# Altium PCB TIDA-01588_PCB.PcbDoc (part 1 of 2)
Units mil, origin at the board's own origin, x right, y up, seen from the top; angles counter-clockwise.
Board outline 787.4 x 472.44 mil, 2 copper layers (Top Layer, Bottom Layer), stack 62 mil thick; 49 components, 26 nets, 145 pads, 54 vias.
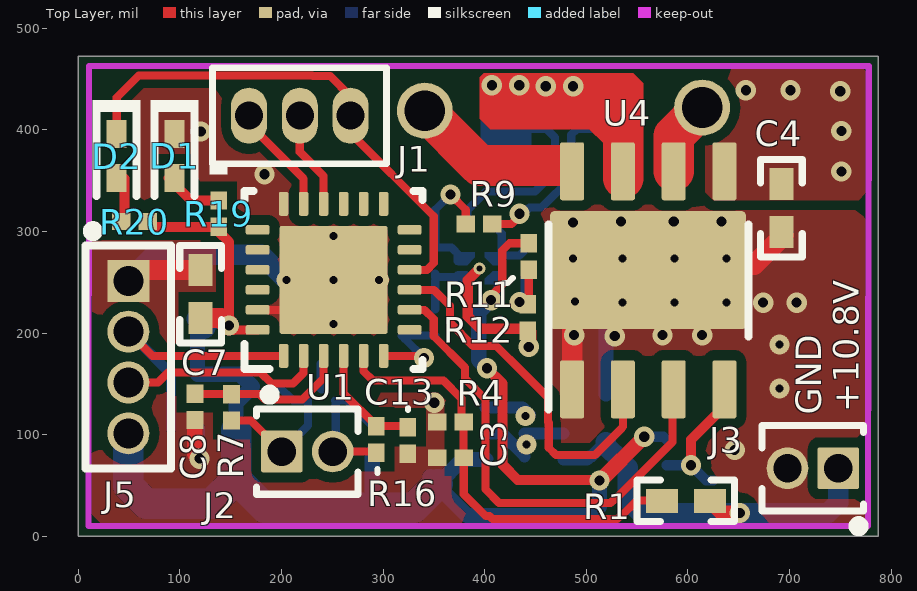
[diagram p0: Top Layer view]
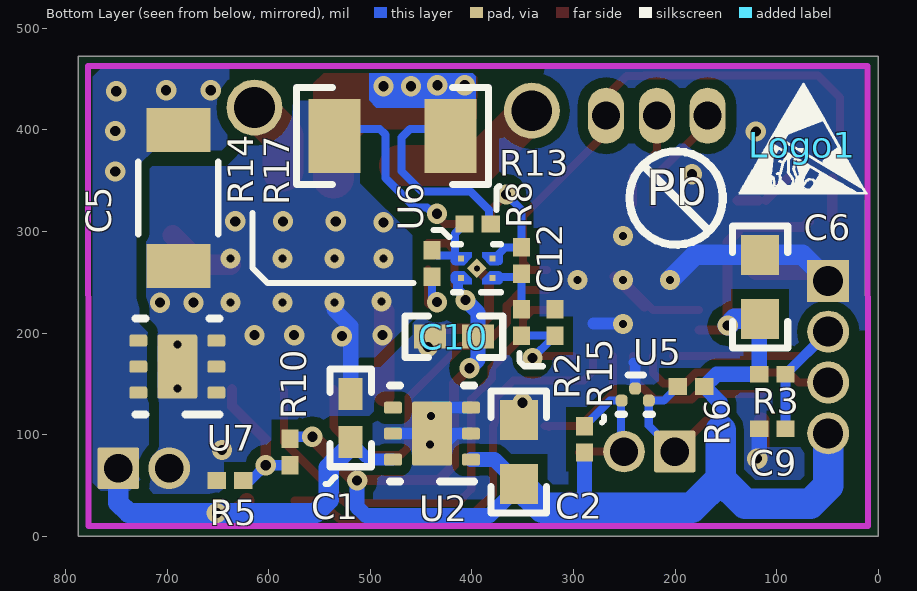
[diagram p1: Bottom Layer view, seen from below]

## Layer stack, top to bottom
Top Solder: solder mask 0.4, Solder Resist, Dk 3.5
Top Layer: signal copper 1.4
Dielectric1: core 59.2, FR-4 High Tg, Dk 4.8
Bottom Layer: signal copper 1.4
Bottom Solder: solder mask 0.4, Solder Resist, Dk 3.5

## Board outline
0,0 0,472.44 787.4,472.44 787.4,0

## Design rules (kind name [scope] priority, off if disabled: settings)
AcuteAngle [All] p1: minimum=4.50000000000000E+0001 checktracksonly=FALSE
AssemblyTestPointUsage [All] p1: valid=2
BoardOutlineClearance BoardOutlineClearance_MountingHoles [OnCopper and InComponentClass('Mounting Holes')] p1: gap=40 ignorepadtopadclearanceinfootprint=FALSE
BoardOutlineClearance BoardOutlineClearance_Poly [OnCopper and IsPoly] p2: gap=10 ignorepadtopadclearanceinfootprint=FALSE
BoardOutlineClearance [OnCopper and Not InComponentClass('Logo') and not InComponentClass('FiducialMark') and not InRegion(1000,500,4000,800) and not InPoly] p3: gap=8 ignorepadtopadclearanceinfootprint=FALSE
Clearance Clearance_1 [IsKeepOut] p1: gap=0 ignorepadtopadclearanceinfootprint=FALSE
Clearance Clearance_Keepouts [((IsTrack Or IsArc) And Not InPoly) And IsFree and IsKeepOut vs ((IsTrack Or IsArc) And Not InPoly) And IsFree and IsKeepOut] p2: gap=0 ignorepadtopadclearanceinfootprint=FALSE
Clearance Clearance_Poly [InPolygon] p3: gap=10 ignorepadtopadclearanceinfootprint=FALSE except(0: Arc-Hole Track-Hole SMDPad-Hole THPad-Hole Via-Hole Fill-Hole Poly-Hole Region-Hole Text-Hole; 8: Track-Poly; 15: Fill-Text Poly-Text Region-Text)
Clearance Clearance_FiducialMark [IsKeepOut and InComponentClass('FiducialMark') vs IsPad and InComponentClass('FiducialMark')] p4: gap=0 ignorepadtopadclearanceinfootprint=FALSE
Clearance [All] p5: gap=7.87 ignorepadtopadclearanceinfootprint=FALSE except(0: Arc-Hole Track-Hole SMDPad-Hole THPad-Hole Via-Hole Fill-Hole Poly-Hole Region-Hole Text-Hole)
ComponentClearance ComponentClearance_MountingHoles_FiducialMarks [InComponentClass('Mounting Holes') vs InComponentClass('FiducialMark')] p1: gap=50 collisioncheckmode=3 verticalgap=10 showdistances=FALSE
ComponentClearance ComponentClearance_Shunt [InComponentClass('Header') vs InComponentClass('Shunt')] p2: gap=0 collisioncheckmode=3 verticalgap=0 showdistances=FALSE
ComponentClearance ComponentClearance_Logo [InComponentClass('Logo')] p3: gap=50 collisioncheckmode=3 verticalgap=10 showdistances=FALSE
ComponentClearance ComponentClearance_ScrewToNut [(HasFootprint('NY PMS 440 0025 PH')) vs (HasFootprint('Keystone_1902C'))] p4: gap=5 collisioncheckmode=3 verticalgap=10 showdistances=FALSE
ComponentClearance ComponentClearance_MountingHoles [InComponentClass('Mounting Holes')] p5: gap=250 collisioncheckmode=3 verticalgap=100000 showdistances=FALSE
ComponentClearance ComponentClearance_SmallPassives [HasFootprint('0201*') or HasFootprint('0402*') or HasFootprint('0508') or HasFootprint('0603*') or HasFootprint('0612') or HasFootprint('0805*') or HasFootprint('0815*') or HasFootprint('0830*') or HasFootprint('1206*') or HasFootprint('1210*') or HasFootprint('1808*') or HasFootprint('1812*') or HasFootprint('1825*') or HasFootprint('2010*') or HasFootprint('2220*') or HasFootprint('2225*') or HasFootprint('2512*') or HasFootprint('2728*') or HasFootprint('3518*') vs HasFootprint('0201*') or HasFootprint('0402*') or HasFootprint('0508') or HasFootprint('0603*') or HasFootprint('0612') or HasFootprint('0805*') or HasFootprint('0815*') or HasFootprint('0830*') or HasFootprint('1206*') or HasFootprint('1210*') or HasFootprint('1808*') or HasFootprint('1812*') or HasFootprint('1825*') or HasFootprint('2010*') or HasFootprint('2220*') or HasFootprint('2225*') or HasFootprint('2512*') or HasFootprint('2728*') or HasFootprint('3518*')] p6: gap=14.96 collisioncheckmode=3 verticalgap=10 showdistances=FALSE
ComponentClearance ComponentClearance_THtoSMT [IsThruComponent vs IsSMTComponent] p7: gap=10 collisioncheckmode=3 verticalgap=10 showdistances=FALSE
ComponentClearance ComponentClearance_THtoTH [IsThruComponent vs IsThruComponent] p8: gap=8 collisioncheckmode=3 verticalgap=8 showdistances=FALSE
ComponentClearance [All] p9: gap=10 collisioncheckmode=3 verticalgap=10 showdistances=FALSE
DiffPairsRouting [All] p1: maxlimit=100 minlimit=10 mostfreqgap=10 toplayer_minwidth=15 toplayer_maxwidth=15 toplayer_prefwidth=15 bottomlayer_minwidth=15 bottomlayer_maxwidth=15 bottomlayer_prefwidth=15 maxuncoupledlength=1000
FabricationTestPointUsage TestPointUsage [All] p1: valid=2 allowmultiple=FALSE
FabricationTestpoint Testpoint [All] p1: side=3 testpointundercomponent=TRUE minsize=40 maxsize=100 preferedsize=60 minholesize=0 maxholesize=40 preferedholesize=32 testpointgrid=1 allowsidetop=TRUE allowsidebottom=TRUE usegrid=TRUE gridtolerance=0.01
FanoutControl Fanout_LCC [IsLCC] p1: bgadir=Out bgaviamode=Centered fanoutstyle=Auto fanoutdirection=Alternating viagrid=1 // Fanout_LCC (Default Rule)
FanoutControl Fanout_BGA [IsBGA] p2: bgadir=Out bgaviamode=Centered fanoutstyle=Auto fanoutdirection=Alternating viagrid=1 // Fanout_BGA (Default Rule)
FanoutControl Fanout_Default [All] p4: bgadir=Out bgaviamode=Centered fanoutstyle=Auto fanoutdirection=Alternating viagrid=1 // Fanout_Default (Default Rule)
FanoutControl Fanout_Small [(CompPinCount < 5)] p5: bgadir=Out bgaviamode=Centered fanoutstyle=Auto fanoutdirection=OutThenIn viagrid=1 // Fanout_Small (Default Rule)
HoleSize [All] p1: absolutevalues=TRUE maxlimit=251 minlimit=7.87 maxpercent=80.000 minpercent=20.000
MinimumAnnularRing MinimumAnnularRing_ThermalPadVias [IsVia and InAnyComponent] p1: minimumring=5.91
MinimumAnnularRing [All] p2: minimumring=8
MinimumSolderMaskSliver MinimumSolderMaskSliver_Logo [InComponentClass('Logo') vs InComponentClass('Logo')] p1: minsoldermaskwidth=0.7
MinimumSolderMaskSliver [All] p2: minsoldermaskwidth=3.94
PlaneConnect [All] p1: planeconnectstyle=Direct reliefexpansion=10 reliefentries=4 reliefconductorwidth=10 reliefairgap=10
PolygonConnect [All] p1: connectstyle=Direct reliefconductorwidth=10 reliefentries=4 polygonreliefangle="90 Angle" airgapwidth=10
RoutingVias ThermalPadVias [IsVia and InAnyComponent] p1: holewidth=7.87 width=19.68 viastyle="Through Hole" minholewidth=7.87 minwidth=19.68 maxholewidth=12.99 maxwidth=23.62
RoutingVias [All] p2: holewidth=10 width=20 viastyle="Through Hole" minholewidth=8 minwidth=18 maxholewidth=12 maxwidth=24
SilkToBoardRegionClearance [Not ((IsComment or IsDesignator) And (Hide <> 'False')) and not InRegion(1000,500,4000,800)] p1:
SilkToSilkClearance SilkToSilkClearance_Pb-FreeLogo [(HasFootprint('Pb-Free_Overlay_Medium') OR HasFootprint('Pb-Free_Overlay_Small')) vs (HasFootprint('Pb-Free_Overlay_Medium') OR HasFootprint('Pb-Free_Overlay_Small'))] p1: silktosilkclearance=0
SilkToSilkClearance [All] p2: silktosilkclearance=4
SilkToSolderMaskClearance SilkToComponentPadClearance [(IsPad or IsFill or IsRegion) and InAnycomponent] p1: minsilkscreentomaskgap=5 clearancetoexposedcopper=TRUE
SilkToSolderMaskClearance "Silk to Solder Mask Opening" [All] p2: minsilkscreentomaskgap=4 clearancetoexposedcopper=FALSE
SolderMaskExpansion [All] p1: expansion=1.97
Width Width_power [InNetClass('Power')] p1: maxlimit=80 minlimit=8 preferedwidth=20
Width [All] p2: maxlimit=40 minlimit=6 preferedwidth=8 checkconnectedcopper=TRUE
15 further rules are at their usual default settings.

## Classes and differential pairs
component class TIDA-01588_E2_Hardware: Logo1 Logo2 ZZ1 ZZ2 ZZ3 ZZ4
component class AssemblyNote: ZZ1 ZZ2 ZZ3 ZZ4
component class Header: J1 J2 J3 J5
component class TIDA-01588_E2_Sheet1: C1 C2 C3 C4 C5 C6 C7 C8 C9 C10 C12 C13 D1 D2 J1 J2 J3 J5 R1 R2 R3 R4 R5 R6 R7 R8 R9 R10 R11 R12 R13 R14 R15 R16 R17 R19 R20 U1 U2 U4 U5 U6 U7

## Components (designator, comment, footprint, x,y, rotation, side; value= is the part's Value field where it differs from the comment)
C1 "GRM155R6YA105ME11D" 0402 519.3,116.5 r90 bottom value=1uF
C2 "C1608JB0J106K080AB" 0603 353.9,83 r270 bottom value=10uF
C3 "GRM033R70J332KA01D" 0201 366.3,77.43 r180 top value=3300pF
C4 "C1005X7R1H104K050BE" 0402 692,323 r90 top value=0.1uF
C5 "C3216X5R1V226M160AC" 1206_180 689,333 r270 bottom value=22uF
C6 "GRM188R60J475KE19D" 0603 116.3,245.5 r90 bottom value=4.7uF
C7 "GRM155R70J104KA01D" 0402 120.3,238.43 r90 top value=0.1uF
C8 "GRM033R71A103KA01D" 0201 114.7,127.5 r270 top value=0.01uF
C9 "GRM033R71A222KA01D" 0201 104.3,105.8 r0 bottom value=2200pF
C10 "GRM155R70J104KA01D" 0402 417.68,196.43 r0 bottom value=0.1uF
C12 "GRM033R70J332KA01D" 0201 318.3,210.43 r90 bottom value=3300pF
C13 "GRM033R71A103KA01D" 0201 324.3,94.43 r270 top value=0.01uF
D1 "SML-LX0402SOC-TR" SML_Orange_0402 94.82,374.27 r90 top value=Green
D2 "SML-LX0402SOC-TR" SML_Orange_0402 37.82,374.27 r90 top value=Red
J1 "GRPB031VWVN-RC" Sullins_GRPB031VWVN-RC 218,414 r0 top
J2 "GRPB021VWVN-RC" Sullins_GRPB021VWVN-RC 225.3,83.43 r0 top
J3 "GRPB021VWVN-RC" Sullins_GRPB021VWVN-RC 723,67 r180 top
J5 "GRPB041VWVN-RC" Sullins_GRPB041VWVN-RC 49.3,176.43 r270 top
Logo1 "ESD Susceptible" ESD_Overlay_small 75,385 r180 bottom
Logo2 "Pb-Free Symbol" Pb-Free_Overlay_small 199,333 r180 bottom
R1 "RC0402JR-072ML" 0402 598,35 r0 top value=2.0Meg
R2 "RC0201JR-07100RL" 0201 351.3,210.5 r270 bottom value=100
R3 "RC0201FR-0747K5L" 0201 104.3,159.43 r0 bottom value=47.5k
R4 "RC0201FR-07619KL" 0201 366.3,112.43 r0 top value=619k
R5 "RC0201FR-073K3L" 0201 638,55 r180 bottom value=3.30k
R6 "RC0201FR-073K3L" 0201 184.31,147.43 r180 bottom value=3.30k
R7 "RC0201JR-07100RL" 0201 150.7,126.96 r90 top value=100
R8 "RC0201FR-0749K9L" 0201 351.3,271.43 r270 bottom value=49.9k
R9 "RC0201FR-072KL" 0201 394.3,307.43 r180 top value=2.00k
R10 "RC0201FR-0716K5L" 0201 579,83 r90 bottom value=16.5k
R11 "RC0201FR-0716K5L" 0201 443.3,275.43 r270 top value=16.5k
R12 "RC0201FR-0710KL" 0201 442.3,215.43 r90 top value=10.0k
R13 "RC0201FR-072KL" 0201 394.3,307.43 r0 bottom value=2.00k
R14 "RC0201FR-0749K9L" 0201 439.3,268.43 r90 bottom value=49.9k
R15 "RC0201FR-073K3L" 0201 289.3,95.5 r270 bottom value=3.30k
R16 "RC0201JR-07100RL" 0201 293.3,95.43 r90 top value=100
R17 "CSR1206FK20L0" 1206 478,394 r180 bottom value=0.02
R19 "RC0201FR-073K3L" 0201 138.3,317.5 r270 top value=3.30k
R20 "RC0201FR-073K3L" 0201 55.31,309.8 r0 top value=3.30k
U1 "MSP430FR2433IRGER" RGE0024H 251.3,252.43 r90 top
U2 "TPS70933DRVR" DRV0006A 439.3,101.08 r0 bottom
U4 "DRV8870DDAR" DDA0008E_N 561,252 r90 top
U5 "ESD122DMXR" DMX0003A 239.3,139.5 r270 bottom
U6 "TLV9061DPW" DPW0005A 395.16,263.88 r0 bottom
U7 "TVS3300DRVR" DRV0006A 690,167 r0 bottom
ZZ1 "This Assembly Note is for PCB labels only" AssemblyNoteLabel -549,2090 r0 top
ZZ2 "These assemblies are ESD sensitive, ESD precautions shall be observed." AssemblyNote -548,1967 r0 top
ZZ3 "These assemblies must be clean and free from flux and all contaminants. Use of no clean flux is not acceptable." AssemblyNote -546,1834 r0 top
ZZ4 "These assemblies must comply with workmanship standards IPC-A-610 Class 2, unless otherwise specified." AssemblyNote -550,1702 r0 top

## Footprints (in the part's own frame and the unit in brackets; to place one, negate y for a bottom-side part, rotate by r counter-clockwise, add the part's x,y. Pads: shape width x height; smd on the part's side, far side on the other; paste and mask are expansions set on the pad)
0201 [mm] "Data from Kemet datasheet CC101_COM dated 7/28/11"
  rect 0.46x0.42 smd mask+0.048: 1(-0.33,0) 2(0.33,0)
  body extent -0.31,-0.16 0.31,0.16, height 0.26
0402 [mm] "0402 from SM-752 data"
  rect 0.8x0.6 smd: 1(-0.6,0) 2(0.6,0)
  silkscreen extent -1.22,-0.52 1.22,0.52, body extent -0.55,-0.3 0.55,0.3, height 0.6
0603 [mm] "0603 from SM-752 data"
  rect 1x0.95 smd: 1(-0.8,0) 2(0.8,0)
  silkscreen extent -1.52,-0.69 1.52,0.69, body extent -0.87,-0.47 0.87,0.47, height 1
1206 [mm] "1206 from SM-752 data"
  rect 1.3x1.85 smd: 1(-1.45,0) 2(1.45,0)
  silkscreen extent -2.4,-1.21 2.4,1.21, body extent -1.7,-0.9 1.7,0.9, height 1.35
1206_180 [mm] "1206_180"
  rect 1.1x1.6 smd: 1(-1.7,0) 2(1.7,0)
  silkscreen extent -0.9,-1 0.9,1, body extent -1.75,-0.95 1.75,0.95, height 1.8
AssemblyNote [mil] "Assembly Note"
AssemblyNoteLabel [mil] "Assembly Note for PCB Labels"
DDA0008E_N [mm]
  rrect17% 1.45x0.6 smd: 1(-2.725,1.905) 2(-2.725,0.635) 3(-2.725,-0.635) 4(-2.725,-1.905) 5(2.725,-1.905) 6(2.725,-0.635) 7(2.725,0.635) 8(2.725,1.905)
  rrect4% 2.4x3.1 on Top Paste: 9(0,0)
  rrect4% 2.4x3.1 on Top Solder: 9(0,0)
  rrect7% 2.95x4.9 smd paste-1.5 mask-1.5: 9(0.252,0.008)
  silkscreen extent -3.22,-2.5 1.4,2.5, body extent -3,-2.45 3,2.45, height 1.57
DMX0003A [mm] "SON, 3-Leads, Body 0.6x1mm"
  rrect67% 0.3x0.3 smd paste-0.045 mask-0.05: 1(-0.15,0) 2(0.15,-0.34) 3(0.15,0.34)
  silkscreen extent -0.49,-0.43 0.49,0.43, body extent -0.3,-0.5 0.3,0.5, height 0.4
DPW0005A [mm] "PX2SON"
  rect 0.15x0.15 smd mask+0: 1(-0.39,0.24) 2(-0.39,-0.24) 4(0.39,-0.24) 5(0.39,0.24)
  rect 0.35x0.35 smd rot 135 paste-0.055 mask-0.05: 3(0,0)
  Top Layer region: -0.55,-0.4 -0.588,-0.392 -0.621,-0.371 -0.642,-0.338 -0.65,-0.3 -0.65,-0.3 -0.65,-0.18 -0.642,-0.142 -0.621,-0.109 -0.588,-0.088 -0.55,-0.08 -0.55,-0.08 -0.319,-0.08 -0.13,-0.269 -0.13,-0.4
  Top Layer region: 0.319,0.08 0.13,0.269 0.13,0.4 0.55,0.4 0.588,0.392 0.621,0.371 0.642,0.338 0.65,0.3 0.65,0.3 0.65,0.18 0.642,0.142 0.621,0.109 0.588,0.088 0.55,0.08 0.55,0.08 0.55,0.08
  Top Layer region: 0.13,-0.4 0.13,-0.269 0.319,-0.08 0.55,-0.08 0.588,-0.088 0.621,-0.109 0.642,-0.142 0.65,-0.18 0.65,-0.18 0.65,-0.3 0.642,-0.338 0.621,-0.371 0.588,-0.392 0.55,-0.4 0.55,-0.4
  Top Layer region: -0.55,0.08 -0.588,0.088 -0.621,0.109 -0.642,0.142 -0.65,0.18 -0.65,0.18 -0.65,0.3 -0.642,0.338 -0.621,0.371 -0.588,0.392 -0.55,0.4 -0.55,0.4 -0.13,0.4 -0.13,0.269 -0.319,0.08
  silkscreen extent -0.6,-0.6 0.6,0.6, body extent -0.42,-0.42 0.42,0.42, height 0.41
DRV0006A [mm] "SON, 6-Leads, Body 2x2mm, Pitch 0.65mm, Thermal Pad 1.6x1mm, TI Recommended"
  rrect33% 0.45x0.3 smd: 1(-0.975,0.65) 2(-0.975,0) 3(-0.975,-0.65) 4(0.975,-0.65) 5(0.975,0) 6(0.975,0.65)
  rrect50% 1x0.7 on Bottom Paste: 7(0,-0.45) 7(0,0.45)
  rrect10% 1x1.6 smd paste-0.5: 7(0,0)
  silkscreen extent -1.05,-1.2 1.05,1.2, body extent -1.05,-1.05 1.05,1.05, height 0.81
ESD_Overlay_small [mil]
  silkscreen extent -62,-48 64,61
Pb-Free_Overlay_small [mil]
  silkscreen extent -46,-46 46,46
RGE0024H [mm] "QFN, 24-Leads, Body 4x4mm, Pitch 0.5mm, Thermal Pad 2.7x2.7mm, TI Recommended"
  rrect42% 0.6x0.24 smd: 1(-1.9,1.25) 2(-1.9,0.75) 3(-1.9,0.25) 4(-1.9,-0.25) 5(-1.9,-0.75) 6(-1.9,-1.25) 13(1.9,-1.25) 14(1.9,-0.75) 15(1.9,-0.25) 16(1.9,0.25) 17(1.9,0.75) 18(1.9,1.25)
  rrect42% 0.24x0.6 smd: 7(-1.25,-1.9) 8(-0.75,-1.9) 9(-0.25,-1.9) 10(0.25,-1.9) 11(0.75,-1.9) 12(1.25,-1.9) 19(1.25,1.9) 20(0.75,1.9) 21(0.25,1.9) 22(-0.25,1.9) 23(-0.75,1.9) 24(-1.25,1.9)
  rrect8% 1.19x1.19 on Top Paste: 25(-0.695,-0.695) 25(-0.695,0.695) 25(0.695,-0.695) 25(0.695,0.695)
  rrect4% 2.7x2.7 smd paste-1.35: 25(0,0)
  silkscreen extent -2.22,-2.22 2.22,2.22, body extent -2.07,-2.07 2.07,2.07, height 1.01
SML_Orange_0402 [mm] "SMD, 2-Leads, Body 1x0.5mm"
  rect 0.7x0.5 smd: 1(-0.55,0) 2(0.55,0)
  silkscreen extent -1,-0.6 1.4,0.6, body extent -0.5,-0.25 0.5,0.25, height 0.5
Sullins_GRPB021VWVN-RC [mil] "Sullins"
  rrect10% 41x41 hole 28: 1(-25,0)
  round 41 hole 28: 2(25,0)
  silkscreen extent -50,-42 50,61, body extent -50,-42 50,42, height 157
Sullins_GRPB031VWVN-RC [mm] "SULLINS"
  oval 0.9x1.4 hole 0.7: 1(-1.27,0) 2(0,0) 3(1.27,0)
  silkscreen extent -2.25,-1.48 2.17,1.2, body extent -2.15,-1.17 2.17,1.17, height 4.2
Sullins_GRPB041VWVN-RC [mm] "TH, Header, 1.27 mm, 4x1, Straight"
  rect 1.05x1.05 hole 0.75: 1(-1.905,0)
  round 1.05 hole 0.75: 2(-0.635,0) 3(0.635,0) 4(1.905,0)
  silkscreen extent -3.25,-1.07 2.79,1.07, body extent -2.79,-1.07 2.79,1.07, height 4.3

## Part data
C1: "CAP, CERM, 1 µF, 35 V,+/- 20%, X5R, 0402", Cap_Case=0402, Manufacturer=MuRata, Supplier Part Number 1=490-10020-1-ND, TempCo=X5R, Tolerance_%=20, Value2=35V, ValueDisplayed=1µF
C2: "CAP, CERM, 10 µF, 6.3 V,+/- 10%, JB, 0603", Cap_Case=0603, Manufacturer=TDK, Supplier Part Number 1=445-11185-1-ND, TempCo=JB, Tolerance_%=10, Value2=6.3V, ValueDisplayed=10µF
C3 C12: "CAP, CERM, 3300 pF, 6.3 V,+/- 10%, X7R, 0201", Cap_Case=0201, Manufacturer=MuRata, Supplier Part Number 1=81-GRM033R70J332KA1D, TempCo=X7R, Tolerance_%=10, Value2=6.3V, ValueDisplayed=3300pF
C4: "CAP, CERM, 0.1 µF, 50 V,+/- 10%, X7R, 0402", Cap_Case=0402, Manufacturer=TDK, Supplier Part Number 1=445-173610-1-ND, TempCo=X7R, Tolerance_%=10, Value2=50V, ValueDisplayed=0.1µF
C5: "CAP, CERM, 22 µF, 35 V,+/- 20%, X5R, 1206", Cap_Case=1206, Manufacturer=TDK, Supplier Part Number 1=445-8045-1-ND, TempCo=X5R, Tolerance_%=20, Value1="0.002398 ohm", Value2=35V, ValueDisplayed=22µF
C6: "CAP, CERM, 4.7 µF, 6.3 V,+/- 10%, X5R, 0603", Cap_Case=0603, Manufacturer=MuRata, Supplier Part Number 1=490-3297-1-ND, TempCo=X5R, Tolerance_%=10, Value1="0.005 ohm", Value2=6.3V, ValueDisplayed=4.7µF
C7 C10: "CAP, CERM, 0.1 µF, 6.3 V,+/- 10%, X7R, 0402", Cap_Case=0402, Manufacturer=MuRata, Supplier Part Number 1=GRM155R70J104KA01D-ND, TempCo=X7R, Tolerance_%=10, Value2=6.3V, ValueDisplayed=0.1µF
C8 C13: "CAP, CERM, 0.01 µF, 10 V,+/- 10%, X7R, 0201", Cap_Case=0201, Manufacturer=MuRata, Supplier Part Number 1=490-3194-1-ND, TempCo=X7R, Tolerance_%=10, Value2=10V, ValueDisplayed=0.01µF
C9: "CAP, CERM, 2200 pF, 10 V,+/- 10%, X7R, 0201", Cap_Case=0201, Manufacturer=MuRata, Supplier Part Number 1=GRM033R71A222KA01D-ND, TempCo=X7R, Tolerance_%=10, Value2=10V, ValueDisplayed=2200pF
D1: "LED, Orange, SMD", Color=Green, Manufacturer=Kingbright, PartNumber=APHHS1005CGCK, Power_TotalModule=0.075, Supplier Part Number 1=754-1101-1-ND, Value1=0.075W, Value2=2.1V
D2: "LED, Orange, SMD", Color=Red, Manufacturer=Kingbright, PartNumber=APHHS1005SURCK, Power_TotalModule=0.075, Supplier Part Number 1=754-1104-1-ND, Value1=0.075W, Value2=1.95V
J1: "Header, 50mil, 3x1, Gold, TH", Color=Black, Manufacturer="Sullins Connector Solutions", Supplier Part Number 1=S9014E-03-ND
J2 J3: "Header, 50mil, 2x1, Gold, TH", Manufacturer="Sullins Connector Solutions", Supplier Part Number 1=S9014E-02-ND
J5: "Header, 50mil, 4x1, Gold, TH", Manufacturer="Sullins Connector Solutions", Supplier Part Number 1=S9014E-04-ND
Logo1: library part ESD_Susceptible, "ESD Susceptible Symbol"
Logo2: library part Pb-Free
R1: library part CRCW04022M00JNED, "RES SMD 2M OHM 5% 1/16W 0402", Manufacturer=Yageo, Power_W=0.063, Supplier Part Number 1=YAG3295CT-ND, TempCo="200 ppm/C", Tolerance_%=5, Value1=5%, Value2=0.063W, Value_Code=2M00, ValueDisplayed=2.0M
R2 R7 R16: "RES, 100, 5%, 0.05 W, 0201", Manufacturer="Yageo America", Power_W=0.05, Supplier Part Number 1=311-100NCT-ND, TempCo="200 ppm/C", Tolerance_%=5, Value1=5%, Value2=0.05W, Value_Code=100R, ValueDisplayed=100
R3: "RES, 47.5 k, 1%, 0.05 W, 0201", Manufacturer="Yageo America", Power_W=0.05, Supplier Part Number 1=YAG2692CT-ND, TempCo="200 ppm/C", Tolerance_%=1, Value1=1%, Value2=0.05W, Value_Code=47k5, ValueDisplayed=47.5k
R4: "RES, 619 k, 1%, 0.05 W, 0201", Manufacturer="Yageo America", Power_W=0.05, Supplier Part Number 1=YAG2750CT-ND, TempCo="200 ppm/C", Tolerance_%=1, Value1=1%, Value2=0.05W, Value_Code=619k
R5 R6 R15 R19 R20: "RES, 3.30 k, 1%, 0.05 W, 0201", Manufacturer="Yageo America", Power_W=0.05, Supplier Part Number 1=YAG2285CT-ND, TempCo="200 ppm/C", Tolerance_%=1, Value1=1%, Value2=0.05W, Value_Code=3k30, ValueDisplayed=3.30k
R8 R14: "RES, 49.9 k, 1%, 0.05 W, 0201", Manufacturer="Yageo America", Power_W=0.05, Supplier Part Number 1=YAG2701CT-ND, TempCo="200 ppm/C", Tolerance_%=1, Value1=1%, Value2=0.05W, Value_Code=49k9, ValueDisplayed=49.9k
R9 R13: "RES, 2.00 k, 1%, 0.05 W, 0201", Manufacturer="Yageo America", Power_W=0.05, Supplier Part Number 1=YAG2280CT-ND, TempCo="200 ppm/C", Tolerance_%=1, Value1=1%, Value2=0.05W, Value_Code=2k00, ValueDisplayed=2.00k
R10 R11: "RES, 16.5 k, 1%, 0.05 W, 0201", Manufacturer="Yageo America", Power_W=0.05, Supplier Part Number 1=YAG2435CT-ND, TempCo="200 ppm/C", Tolerance_%=1, Value1=1%, Value2=0.05W, Value_Code=16k5, ValueDisplayed=16.5k
R12: "RES, 10.0 k, 1%, 0.05 W, 0201", Manufacturer="Yageo America", Power_W=0.05, Supplier Part Number 1=311-10.0KMCT-ND, TempCo="200 ppm/C", Tolerance_%=1, Value1=1%, Value2=0.05W, Value_Code=10k0, ValueDisplayed=10.0k
R17: "RES, 0.02, 1%, 0.5 W, 1206", Manufacturer="Stackpole Electronics Inc", Power_W=0.5, Supplier Part Number 1=CSR1206FK20L0CT-ND, TempCo="100 ppm/C", Tolerance_%=1, Value1=1%, Value2=0.5W, Value_Code=R020, ValueDisplayed=0.02
U1: "MSP430FR2433 16 MHz Ultra-Low-Power Microcontroller with 16 KB FRAM, 4 KB RAM, 19 IO, 4 Timers, RGE0024H (VQFN-24)", Alternate Manufacturer="Texas Instruments", Alternate PartNumber=MSP430FR2433IRGET
U2: "150-mA, 30-V, Ultra-Low IQ, Wide Input Low-Dropout Regulator with Reverse Current Protection, DRV0006A (WSON-6)", Alternate Manufacturer="Texas Instruments", Alternate PartNumber=TPS70933DRVT
U4: "3.6A Brushed DC Motor Driver (PWM Ctrl), DDA0008E (SOIC-8)", Alternate Manufacturer="Texas Instruments", Alternate PartNumber=DRV8870DDA
U5: "2-Channel ESD Protection Diode for USB Type-C and HDMI 2.0, DMX0003A (X2SON-3)", Alternate Manufacturer="Texas Instruments"
U6: "TLV9061DPW, DPW0005A (X2SON-5)", Alternate Manufacturer="Texas Instruments"
U7: "33V Precision Surge Protection Clamp, DRV0006A (WSON-6)", Alternate Manufacturer="Texas Instruments", Alternate PartNumber=TVS3300DRVT
ZZ1: library part AssemblyNoteLabel, Alternate Manufacturer=-
ZZ2 ZZ3 ZZ4: library part AssemblyNote, Alternate Manufacturer=-

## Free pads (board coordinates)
  round 55 hole 40: 1(341,419) 1(614,422)

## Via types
v1: diameter 20, hole 10, Top Layer to Bottom Layer, tented both sides, 28 vias
v2: diameter 19.68, hole 7.87, Top Layer to Bottom Layer, 17 vias
v3: diameter 20, hole 10, Top Layer to Bottom Layer, 8 vias
v4: diameter 12, hole 6, Top Layer to Bottom Layer, 1 vias

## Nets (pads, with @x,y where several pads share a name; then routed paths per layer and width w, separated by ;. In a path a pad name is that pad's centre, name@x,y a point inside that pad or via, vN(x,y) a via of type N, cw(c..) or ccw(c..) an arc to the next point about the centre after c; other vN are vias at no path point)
3.3V: C2.2 C6.1 C7.1 C10.1 J5.4 R3.2 R6.2 R10.2 R11.1 R15.2 R19.2 R20.2 U1.24 U2.1 U6.5 | length 1651.2
  Top Layer w8: v1@409.18,239.49 417.3,247.61 417.3,281.43 424.29,288.42 R11.1@443.3,288.42
  Top Layer w9: v1@152.51,203.21 U1.24@176.5,203.21
  Top Layer w10: R20.2@68.3,309.8 73.59,304.51 R19.2@138.3,304.51 ; R19.2@138.3,299.8 148.3,289.8 v1(148.3,207.43) v1@152.51,203.21 ; v1(402.3,165.5) 417.58,150.21 417.58,70.5 432.58,55.5 513.5,55.5 v1(513,55)
  Top Layer w15: v1(513,55) 514,55 v1(557,98)
  Top Layer w20: C7.1@120.3,214.8 140.92,214.8 v1(148.3,207.43)
  Bottom Layer w10: v1(406.3,232.5) 406.3,234.85 413.58,242.12 413.58,251.36 ; v1(557,98) 576,98 R10.2@579,95
  Bottom Layer w15: C6.1@123.7,204 117.29,197.59 R3.2@117.29,159.43 159.32,159.43 R6.2@171.32,147.43 155.31,131.42 155.31,104.43 ; 289,28 289.3,28.3 R15.2@289.3,82.51 ; C2.2@346.5,58.9 C2.2@353.9,51.5 ; U2.1@400.92,75.49 377.89,75.49 C2.2@353.9,51.5 ; v1(402.3,165.5) 394.06,173.74 C10.1@394.06,196.43 394.06,220.25 v1(406.3,232.5) ; v1(513,55) 513,29 504.5,20.5 382.44,20.5 353.9,49.04 C2.2@353.9,51.5
  Bottom Layer w20: C6.1@116.3,214 141.73,214 v1(148.3,207.43) ; C6.1@123.7,204 C6.1@125,205.3
  Bottom Layer w30: J5.4@49.3,101.43 49.3,49.7 67,32 131.04,32 155.31,56.27 ; 155.31,104.43 155.31,56.27 ; C2.2@353.9,51.5 330.4,28 289,28 183.58,28 155.31,56.27
DC_BUS: C3.1 R1.1 R4.2 U1.5 | length 430.3
  Top Layer w8: U1.5@280.83,177.62 280.83,162.43 289.88,153.37 359.36,153.37 376.83,135.9 377.29,135.9 R4.2@377.29,112.5 ; C3.1@378.29,74.5 C3.1@378.29,77.5 ; R4.2@378.29,109.49 379.29,108.49 C3.1@379.29,77.43 379.3,41.7 401,20 404.55,20 407.55,17 530.38,17 533.38,20 534.38,20 549.69,35.31 574.07,35.31 R1.1@574.38,35
ENC_B: C13.1 R16.2 U1.4 | length 118.9
  Top Layer w8: U1.4@261.14,177.62 261.14,140.58 R16.2@293.3,108.42 C13.1@323.3,108.42 ; C13.1@324.3,107.42 C13.1@323.3,108.42 ; C13.1@328.3,108.42 C13.1@323.3,108.42
ENCODER_A: J2.1 R6.1 R7.1 U5.3 | length 157.4
  Top Layer w8: R7.1@150.7,113.97 169.76,113.97 J2.1@200.3,83.43
  Bottom Layer w8: R6.1@197.3,147.43 211.14,133.59 U5.3@225.92,133.59 225.92,109.04 J2.1@200.3,83.43
ENCODER_B: J2.2 R15.1 R16.1 U5.2 | length 149.6
  Top Layer w8: J2.2@251.29,82.43 J2.2@250.3,83.43 293.31,83.43 R16.1@294.3,82.43
  Bottom Layer w8: U5.2@252.69,133.59 264.2,133.59 R15.1@289.3,108.49 ; U5.2@253.41,133.23 253.41,86.54 J2.2@250.3,83.43 J2.2@254.3,87.43
FAULT: D2.2 J1.3 U1.10 | length 507.9
  Top Layer w8: D2.2@37.82,395.93 37.82,431.82 59.43,453.43 230.26,453.43 230.69,453 248,453 268,433 J1.3@268,414 268,396.82 349.79,315.03 349.79,268.91 343.14,262.27 U1.10@326.1,262.27
I_OUT: C12.1 R2.2 U1.6 | length 104.9
  Top Layer w8: U1.6@300.51,177.62 338.1,177.62 v1(340.3,175.43)
  Bottom Layer w8: C12.1@318.3,197.43 C12.1@321.3,194.43 ; v1(340.3,175.43) C12.1@321.3,194.43 ; R2.2@351.3,197.51 321.3,197.51 C12.1@321.3,194.43
IN1: U1.8 U4.3 | length 483
  Top Layer w8: U1.8@326.1,222.9 340.9,222.9 349.79,214.01 349.79,196.87 380.43,166.24 380.43,155.22 400.71,134.94 400.71,46.29 414.13,32.87 523.81,32.87 526.81,35.87 527.81,35.87 584.87,92.94 584.87,143.59 U4.3@586,144.72
IN2: U1.9 U4.2 | length 364
  Top Layer w8: U1.9@326.1,242.58 350.06,242.58 365.66,226.98 365.66,210.27 388.56,187.37 411.36,187.37 424.18,174.56 424.31,174.56 462.31,136.55 462.31,112.43 463.02,111.73 463.02,87.21 470.22,80 508.35,80 535.13,106.77 535.13,107.06 536,107.93 U4.2@536,144.72
NetD1_1: D1.1 R19.1 | length 51
  Top Layer w10: D1.1@88.82,352.62 110.48,330.96 ; 117.95,330.49 R19.1@138.3,330.49
NetD2_1: D2.1 R20.1 | length 43.6
  Top Layer w10: R20.1@42.32,309.8 45.3,312.78 D2.1@45.3,352.14
NetR2_1: R2.1 R8.2 U6.1 | length 54.7
  Bottom Layer w8: R2.1@351.3,223.49 R8.2@351.3,251.51 ; R8.2@351.3,258.43 351.3,255.15 374.75,255.15
NetR5_2: R5.2 R10.1 U4.4 | length 140.6
  Top Layer w10: v1(603,70) 603,95 636,128 U4.4@636,144.72
  Bottom Layer w10: R10.1@579,70.01 v1(603,70) 618,55 R5.2@625.01,55
NetR8_1: R8.1 R9.2 U6.2 | length 121.7
  Top Layer w8: v1(366.3,336.43) 381.31,321.42 R9.2@381.31,307.43
  Bottom Layer w8: v1(366.3,336.43) 351.3,321.43 R8.1@351.3,284.42 367.21,284.42 375.94,275.68
NetR11_2: R11.2 R12.2 R14.1 | length 70.7
  Top Layer w8: v1@433.06,228.42 R12.2@442.3,228.42 443.3,229.42 R11.2@443.3,262.43
  Bottom Layer w8: v1(434.3,230.5) 439.3,235.5 R14.1@439.3,255.43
